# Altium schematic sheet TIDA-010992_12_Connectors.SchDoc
size 431 x 279 mm; Date: Not shown in title block; ApprovedBy: Not shown in title block; CheckedBy: Not shown in title block; Author: Not shown in title block; CompanyName: Not shown in title block; Engineer: Not shown in title block; Organization: Not shown in title block; Address1: Not shown in title block; Address2: Not shown in title block; Address3: Not shown in title block; Address4: Not shown in title block; DocumentNumber: 12; Revision: Use project parameter SCH_Rev; SheetNumber: 12; SheetTotal: 13; PageSetup: Record=PageOptions¦CenterHorizontal=True¦CenterVertical=True¦PrintScale=1.00¦XCorrection=1.00¦YCorrection=1.00¦PrintKind=0¦BorderSize=5000000¦LeftOffset=0¦BottomOffset=0¦Orientation=2¦PaperLength=1000¦PaperWidth=1000¦Scale=100¦PaperSource=15¦PrintQuality=600¦MediaType=1¦DitherType=10¦PaperKind=Letter¦PrintScaleMode=1
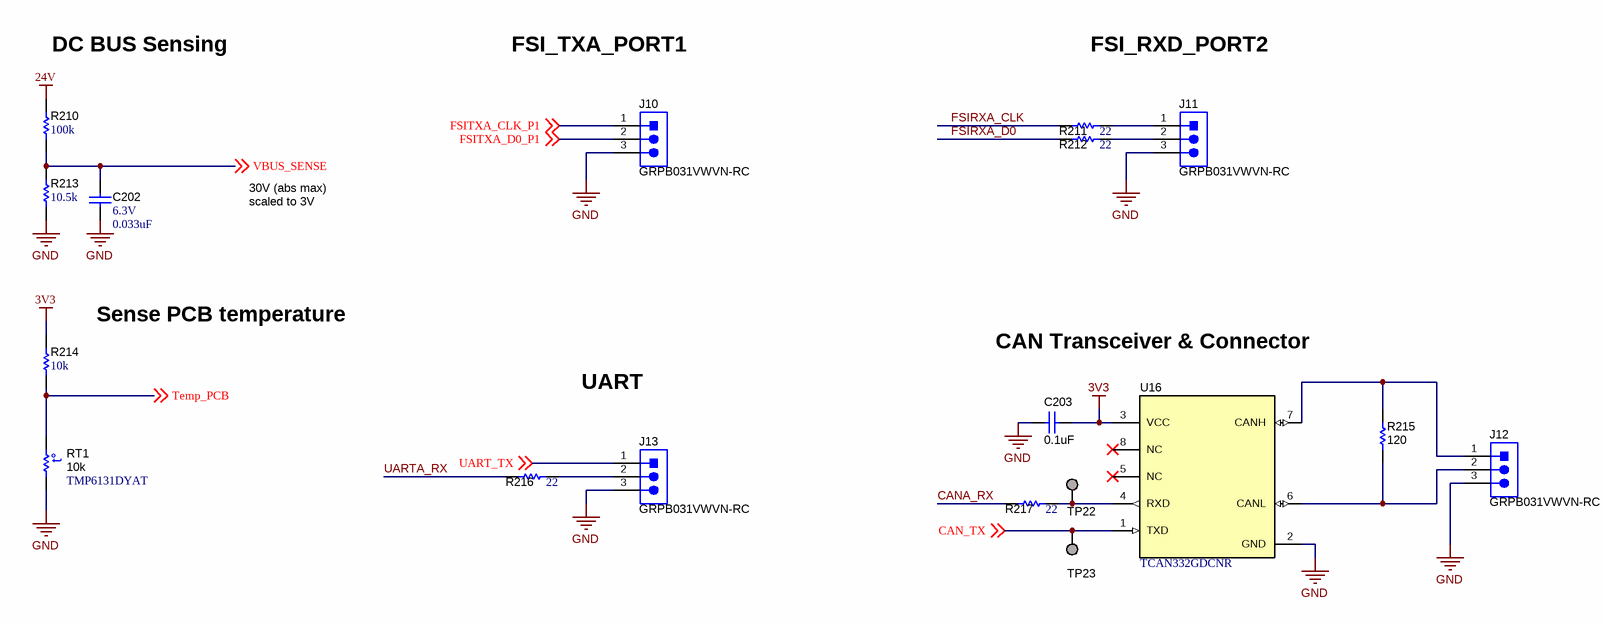
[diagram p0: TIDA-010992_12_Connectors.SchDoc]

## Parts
C202  VDC_V: 6.3V  ValueDisplayed: 0.033uF  [0201]  (hidden comment: GRM033R60J333KE01D)
C203  ValueDisplayed: 0.1uF  [0402]  (hidden comment: 885012205037)
J10  GRPB031VWVN-RC  [Sullins_GRPB031VWVN-RC]
J11  GRPB031VWVN-RC  [Sullins_GRPB031VWVN-RC]
J12  GRPB031VWVN-RC  [Sullins_GRPB031VWVN-RC]
J13  GRPB031VWVN-RC  [Sullins_GRPB031VWVN-RC]
R210  ValueDisplayed: 100k  [0402]  (hidden comment: CMP-0025950-3)
R211  ValueDisplayed: 22  [0201]  (hidden comment: ERJ-1GNJ220C)
R212  ValueDisplayed: 22  [0201]  (hidden comment: ERJ-1GNJ220C)
R213  ValueDisplayed: 10.5k  [0402]  (hidden comment: RC0402FR-0710K5L)
R214  ValueDisplayed: 10k  [0402]  (hidden comment: CMP-0026825-5)
R215  ValueDisplayed: 120  [0603]  (hidden comment: RC0603FR-07120RL)
R216  ValueDisplayed: 22  [0201]  (hidden comment: ERJ-1GNJ220C)
R217  ValueDisplayed: 22  [0201]  (hidden comment: ERJ-1GNJ220C)
RT1  value 10k  [DYA0002A-MFG]  (hidden comment: TMP6131DYAT)
TP22  TESTPOINT  [TP_25MIL-SMT]  (value not drawn)  (no BOM)
TP23  TESTPOINT  [TP_25MIL-SMT]  (value not drawn)  (no BOM)
U16  TCAN332GDCNR  [DCN0008A_N]

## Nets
3V3: C203.2 R214.2 U16.3(VCC)
24V: R210.2
GND: C202.2 C203.1 J10.3 J11.3 J12.3 J13.3 R213.1 RT1.1 U16.2(GND)
CAN_TX: TP23.1 U16.1(TXD) ; off-sheet CAN_TX
CANA_RX: R217.1
FSIRXA_CLK: R211.1
FSIRXA_D0: R212.1
FSITXA_CLK_P1: J10.1 ; off-sheet FSITXA_CLK_P1
FSITXA_D0_P1: J10.2 ; off-sheet FSITXA_D0_P1
Temp_PCB: R214.1 RT1.2 ; off-sheet Temp_PCB
UART_TX: J13.1 ; off-sheet UART_TX
UARTA_RX: R216.1
VBUS_SENSE: C202.1 R210.1 R213.2 ; off-sheet VBUS_SENSE
NetJ11_1: J11.1 R211.2
NetJ11_2: J11.2 R212.2
NetJ12_1: J12.1 R215.2 U16.7(CANH)
NetJ12_2: J12.2 R215.1 U16.6(CANL)
NetJ13_2: J13.2 R216.2
NetR217_2: R217.2 TP22.1 U16.4(RXD)

Not connected (* = marked no-connect by the designer): U16 5(NC)* 8(NC)*

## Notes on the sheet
- DC BUS Sensing
- FSI_TXA_PORT1
- FSI_RXD_PORT2
- 30V (abs max) scaled to 3V
- Sense PCB temperature
- UART
- CAN Transceiver & Connector

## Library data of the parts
C202 = CMP-0009699-1: CAP, CERM, 0.033 uF, 6.3 V, +/- 10%, X5R, 0201; Manufacturer: MuRata; TaMin_C: -55°C; Polarized: N; SizeAreaWB_mm2: 2.08; Value1: Unknown; U/M: EA; TaMax_C: 85°C; SizeZ_mm: 0.26; SizeX_mm: 0.6; SizeY_mm: 0.3; SizeArea_mm2: 0.18; Cap_F: 33nF; AEC Category: Q200
C203 = CMP-0006228-2: CAP, CERM, 0.1 uF, 16 V, +/- 10%, X7R, 0402; Manufacturer: Wurth Elektronik; TaMin_C: -55°C; Polarized: N; SizeAreaWB_mm2: 3; Value1: Unknown; U/M: EA; Value: 0.1uF; TaMax_C: 125°C; SizeZ_mm: 0.6; SizeX_mm: 1; SizeY_mm: 0.5; Value2: 16V; Cap_F: 100nF; AEC Category: Q200
J10-J13 = CMP-0054564-1: Header, 50mil, 3x1, Gold, TH; Manufacturer: Sullins Connector Solutions; CNHeader: TRUE; Green_Lifecycle: Not Set; Shrouded: N; Gender: Male; Green_REACh: Incomplete; Row_Count: 1; CT: FALSE
R210 = CMP-0025950-3: RES, 100 k, 1%, 0.063 W, AEC-Q200 Grade 0, 0402; PartNumber: CRCW0402100KFKED; Manufacturer: Vishay-Dale; Value: 100k; Power_W: 63mW; Value2: 0.063W; VDC_V: 50V; TempCo: 100 ppm/C; EIA_Code: E96; AEC Category: Q200; AEC Qualified: Y; AEC Grade: 0; SizeArea_mm2: 0.5; SizeX_mm: 1; SizeZ_mm: 0.6
R211 R212 R216 R217 = CMP-0027015-3: RES, 22, 5%, 0.05 W, AEC-Q200 Grade 1, 0201; Manufacturer: Panasonic; Power_W: 50mW; TempCo: 200 ppm/C; Value_Code: 22R0; U/M: EA; Value: 22; EIA_Code: E24; SizeX_mm: 0.6; SizeY_mm: 0.3; SizeZ_mm: 0.26; Value2: 0.05W; SizeArea_mm2: 0.18; AEC Qualified: Y; AEC Grade: 1; AEC Category: Q200
R213 = CMP-0078781-1: RES, 10.5 k, 1%, 0.063 W, 0402; Manufacturer: Yageo America; Value_Code: 10k5; SizeArea_mm2: 0.5; AEC Qualified: N; AEC Category: Q200; Value: 10.5k; SizeZ_mm: 0.6; EIA_Code: E96; TempCo: 100 ppm/C; Power_W: 63mW; VDC_V: 50V; Value2: 0.063W; SizeX_mm: 1
R214 = CMP-0026825-5: RES, 10 k, 5%, 0.063 W, AEC-Q200 Grade 0, 0402; PartNumber: CRCW040210K0JNED; Manufacturer: Vishay-Dale; Value: 10k; Value_Code: 10k0; Power_W: 63mW; Value2: 0.063W; VDC_V: 50V; TempCo: 200 ppm/C; SizeArea_mm2: 0.5; SizeX_mm: 1; SizeZ_mm: 0.6; EIA_Code: E24; AEC Category: Q200; AEC Qualified: Y; AEC Grade: 0
R215 = CMP-0022769-3: RES, 120, 1%, 0.1 W, 0603; Manufacturer: Yageo America; Value: 120; Value_Code: 120R; Power_W: 100mW; Value2: 0.1W; VDC_V: 150V; TempCo: 200 ppm/C; SizeArea_mm2: 1.28; SizeX_mm: 1.6; SizeY_mm: 0.8; SizeZ_mm: 1; U/M: EA; AEC Category: Q200
RT1 = CMP-0091865-2: ±1% tolerance 10kΩ linear thermistor available in 0402 and 0603 package options 2-SOT-5X3 -40 to 125; Manufacturer: Texas Instruments; Max Current: 400uA; AEC Qualified: No; TJmax_C: +155°C; TaMin_C: -40°C; TempCo: 6400ppm/°C; TaMax_C: +125°C; VDC_V: 5.5V; SizeZ_mm: 0.77mm; AEC Category: Q200; CompType: IC
TP22 TP23 = CMP-0078143-3: TEST POINT.  No entry in BOM.
U16 = CMP-0080976-2: 3.3-V CAN Transceivers with CAN FD (Flexible Data Rate), DCN0008A (SOT-23-8); Alternate PartNumber: TCAN332GDCNT; Alternate Manufacturer: Texas Instruments; SizeAreaWB_mm2: 15.21; SizeZ_mm: 1.1; SizeX_mm: 2.9; SizeArea_mm2: 8.41; CompType: IC; AEC Qualified: N; AEC Category: Q200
